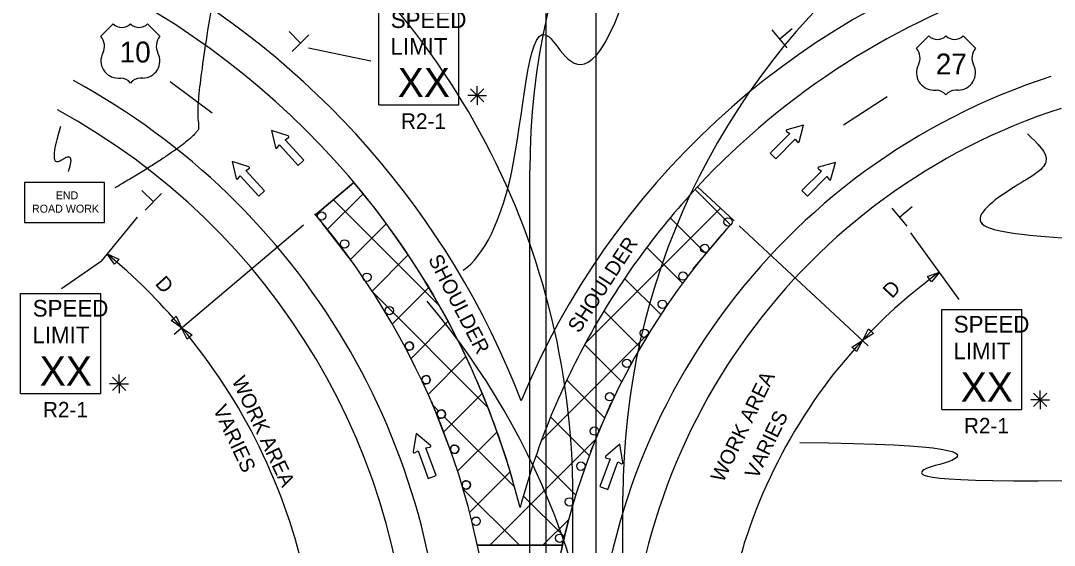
# Model space of a CAD drawing. Extents: x 16452 to 19504, y 5713 to 7079.
# Drawn here: x 16729 to 17224.4, y 6501.7 to 6753 of the extents above; entities that cross this region are included whole.
import ezdxf

# ---------------------------------------------------------------- set-up
doc = ezdxf.new("R2010")
doc.units = 0
for name, color, linetype in [('ALI_LEGAL_EX', 7, 'Continuous'), ('MT_SCRATCH_LEVEL_A', 7, 'Continuous'), ('MT_SCRATCH_LEVEL_E', 7, 'Continuous'), ('PAVT_EDGE_EX', 7, 'Continuous'), ('TRAFFIC_SIGNS_PR', 7, 'Continuous'), ('TYPICAL_EX', 7, 'Continuous'), ('TYPICAL_TEXT_DIMEN_PR', 7, 'Continuous')]:
    doc.layers.add(name, color=color, linetype=linetype)

msp = doc.modelspace()

# ---------------------------------------------------------------- linework, layer by layer
at = {"layer": 'ALI_LEGAL_EX'}
for p, q in [((16980.68, 7015.93), (16980.68, 6197.8)), ((17004.68, 7015.93), (17004.68, 6197.8)), ((16980.68, 6877.04), (16980.68, 6013.12)), ((17004.68, 6877.04), (17004.68, 6013.12)), ((16973.01, 6180.85), (16973.01, 6681.19)), ((16993.65, 6024.8), (16993.65, 6525.15)), ((17017.65, 6024.8), (17017.65, 6525.15))]:
    msp.add_line(p, q, dxfattribs=at)
for points in [[(16820.7, 6708.79), (16800.68, 6723.77)], [(17123.3, 6703.07), (17144.27, 6716.68)], [(16888.99, 6636.13), (16873.66, 6655.88)], [(17051.33, 6634.12), (17067.47, 6653.22)], [(16935.03, 6547.11), (16925.96, 6570.4)], [(17002.2, 6546.89), (17011.97, 6569.9)]]:
    msp.add_lwpolyline(points, dxfattribs=at)
for centre, radius, start, end in [((17313.01, 6681.19), 340, 129.5666, 180), ((16629.65, 6525.15), 364, 0, 57.2958), ((17357.65, 6525.15), 340, 129.5666, 180), ((16591.93, 6425.58), 364, 0, 40.1909), ((17319.93, 6425.58), 340, 137.516, 180), ((16645.75, 6383.76), 364, 0, 40.1909)]:
    msp.add_arc(centre, radius, start, end, dxfattribs=at)
at = {"layer": 'MT_SCRATCH_LEVEL_A'}
for p, q in [((16870.35, 6660.05), (16888.71, 6675.51)), ((16876.07, 6653.08), (16893.14, 6670.15)), ((17069.18, 6655.19), (17052.19, 6672.18)), ((17070.93, 6657.09), (17053.35, 6673.43)), ((16929.73, 6616.45), (16878.92, 6667.26)), ((16999.56, 6598.38), (17064.37, 6663.19)), ((16887.07, 6638.62), (16904.25, 6655.8)), ((17057.35, 6641.57), (17040.31, 6658.61)), ((17046.21, 6627.26), (17029.06, 6644.41)), ((16897.41, 6623.51), (16914.74, 6640.84)), ((17035.76, 6612.25), (17018.45, 6629.55)), ((16907.08, 6607.72), (16924.61, 6625.25)), ((16952.92, 6567.81), (16897.76, 6622.96)), ((17026.03, 6596.52), (17008.52, 6614.04)), ((16916.05, 6591.23), (16933.83, 6609.01)), ((16978.56, 6551.92), (17030.3, 6603.66)), ((17017.05, 6580.05), (16999.27, 6597.83)), ((16924.29, 6574.02), (16942.38, 6592.11)), ((17008.85, 6562.79), (16990.74, 6580.9)), ((16931.75, 6556.03), (16950.22, 6574.49)), ((16929.2, 6566.08), (16926.64, 6568.63)), ((16965.75, 6529.53), (16932.02, 6563.25)), ((17001.48, 6544.7), (16982.96, 6563.22)), ((16938.39, 6537.21), (16957.31, 6556.13)), ((16953.81, 6501.72), (17004.45, 6552.36)), ((16995.01, 6525.72), (16975.99, 6544.74)), ((16944.13, 6517.5), (16963.6, 6536.96)), ((16968.1, 6501.72), (16940.97, 6528.84)), ((16989.56, 6505.71), (16969.88, 6525.39)), ((16979.27, 6501.72), (16991.66, 6514.11)), ((16991.51, 6513.55), (16988.57, 6501.72))]:
    msp.add_line(p, q, dxfattribs=at)
for points in [[(16888.71, 6675.51), (16888.71, 6675.51), (16870.35, 6660.05)], [(17070.93, 6657.09), (17053.35, 6673.43), (17053.35, 6673.43)], [(16968.33, 6519.76), (16968.33, 6519.76), (16968.33, 6519.76)], [(16968.33, 6519.76), (16968.33, 6519.76)], [(16947.88, 6501.72), (16988.57, 6501.72), (16991.51, 6513.55)]]:
    msp.add_lwpolyline(points, dxfattribs=at)
for centre, radius, start, end in [((16591.93, 6425.58), 388, 28.2673, 40.102), ((17319.93, 6425.58), 364, 137.0843, 151.1372), ((16591.93, 6425.58), 388, 14.0483, 28.2673), ((16591.93, 6425.58), 388, 14.0483, 28.2673), ((16591.93, 6425.58), 388, 14.0483, 28.2673), ((17319.93, 6425.58), 364, 151.1372, 165.0045), ((17319.93, 6425.58), 364, 151.1372, 165.0044), ((17319.93, 6425.58), 364, 151.1372, 165.0044), ((16915.23, 6597.14), 2, 90, 205.9785), ((16915.23, 6597.14), 2, 209.93, 270), ((16915.23, 6597.14), 2, 270, 90), ((16923.27, 6581.04), 2, 90, 203.3612), ((16923.27, 6581.04), 2, 206.9117, 270), ((16923.27, 6581.04), 2, 270, 90), ((16930.51, 6564.57), 2, 90, 200.7992), ((16930.51, 6564.57), 2, 270, 90), ((16930.51, 6564.57), 2, 203.838, 270), ((16936.94, 6547.75), 2, 90, 198.3282), ((16936.94, 6547.75), 2, 200.6735, 270), ((16936.94, 6547.75), 2, 270, 90), ((16942.52, 6530.65), 2, 90, 196.0905), ((16942.52, 6530.65), 2, 270, 90), ((16942.52, 6530.65), 2, 197.2755, 270), ((17319.93, 6425.58), 364, 165.00447777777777, 165.0044972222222), ((16591.93, 6425.58), 388, 14.048225, 14.048227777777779), ((17319.93, 6425.58), 364, 165.0044, 165.0045)]:
    msp.add_arc(centre, radius, start, end, dxfattribs=at)
at = {"layer": 'MT_SCRATCH_LEVEL_E'}
for p, q in [((16857.2, 6697.82), (16849.25, 6700.35)), ((16849.25, 6700.35), (16851.12, 6692.23)), ((17097.56, 6698.96), (17088.21, 6689.56)), ((17096.08, 6699.99), (17097.56, 6698.96)), ((17104.24, 6703.05), (17096.22, 6700.81)), ((17102.07, 6694.99), (17104.24, 6703.05)), ((16855.79, 6696.02), (16857.31, 6696.99)), ((16864.75, 6686.25), (16855.79, 6696.02)), ((17090.86, 6686.92), (17100.21, 6696.32)), ((17100.21, 6696.32), (17101.25, 6694.84)), ((16851.94, 6692.05), (16853.03, 6693.49)), ((16853.03, 6693.49), (16862, 6683.72)), ((17088.21, 6689.56), (17090.86, 6686.92)), ((16838.3, 6683.02), (16830.35, 6685.55)), ((16830.35, 6685.55), (16832.22, 6677.44)), ((16862, 6683.72), (16864.75, 6686.25)), ((17119.47, 6685.09), (17111.45, 6682.86)), ((17117.3, 6677.03), (17119.47, 6685.09)), ((16836.89, 6681.22), (16838.41, 6682.19)), ((16845.86, 6671.46), (16836.89, 6681.22)), ((17112.79, 6681), (17103.44, 6671.6)), ((17111.31, 6682.03), (17112.79, 6681)), ((16833.04, 6677.26), (16834.14, 6678.69)), ((16834.14, 6678.69), (16843.1, 6668.93)), ((17106.09, 6668.96), (17115.44, 6678.36)), ((17115.44, 6678.36), (17116.48, 6676.89)), ((16843.1, 6668.93), (16845.86, 6671.46)), ((17103.44, 6671.6), (17106.09, 6668.96))]:
    msp.add_line(p, q, dxfattribs=at)
for centre, start, end in [((17096.35, 6700.36), 105.5821, 235.121), ((16857.05, 6697.37), 302.594, 72.331), ((17101.62, 6695.12), 215.1934, 344.9303), ((16851.57, 6692.34), 192.9827, 322.5217), ((16838.15, 6682.58), 302.594, 72.331), ((17111.58, 6682.41), 105.5821, 235.121), ((16832.67, 6677.55), 192.9827, 322.5217), ((17116.85, 6677.16), 215.1934, 344.9303)]:
    msp.add_arc(centre, 0.463, start, end, dxfattribs=at)
at = {"layer": 'PAVT_EDGE_EX'}
msp.add_line((16988.57, 6501.72), (16947.88, 6501.72), dxfattribs=at)
for centre, radius, start, end in [((17319.93, 6425.58), 380, 107.923, 157.5011), ((16591.93, 6425.58), 404, 21.0961, 61.4862), ((17319.93, 6425.58), 364, 107.923, 137.0843), ((16591.93, 6425.58), 388, 14.0482, 61.4862), ((16591.93, 6425.58), 340, 0, 61.4862), ((17319.93, 6425.58), 316, 107.923, 180), ((16591.93, 6425.58), 324, 0, 61.4862), ((17319.93, 6425.58), 300, 107.923, 180), ((17319.93, 6425.58), 340, 167.0592, 180)]:
    msp.add_arc(centre, radius, start, end, dxfattribs=at)
at = {"layer": 'TRAFFIC_SIGNS_PR'}
for p, q in [((16900.57, 6712.64), (16900.57, 6760.64)), ((16938.97, 6712.64), (16938.97, 6760.64)), ((16900.57, 6712.64), (16938.97, 6712.64)), ((16728.95, 6622.41), (16767.35, 6622.41)), ((16728.95, 6574.41), (16728.95, 6622.41)), ((16767.35, 6574.41), (16767.35, 6622.41)), ((17170.41, 6614.75), (17208.81, 6614.75)), ((17170.41, 6566.75), (17170.41, 6614.75)), ((17208.81, 6566.75), (17208.81, 6614.75)), ((16728.95, 6574.41), (16767.35, 6574.41)), ((17170.41, 6566.75), (17208.81, 6566.75))]:
    msp.add_line(p, q, dxfattribs=at)
msp.add_lwpolyline([(16730.76, 6656.32), (16769.16, 6656.32), (16769.16, 6675.52), (16730.76, 6675.52)], close=True, dxfattribs=at)
for centre in [(16873.23, 6659.48), (17067.98, 6656.63), (16884.19, 6646.08), (17056.86, 6643.93), (16894.93, 6630.13), (17046.37, 6630.65), (16905.68, 6614.18), (17036.58, 6617.2), (17027.91, 6603.29), (16915.23, 6597.14), (17019.45, 6588.91), (16923.27, 6581.04), (17011.28, 6572.88), (16930.51, 6564.57), (17003.96, 6556.44), (16936.94, 6547.75), (16997.51, 6539.63), (16942.52, 6530.65), (16991.96, 6522.51), (16947.27, 6513.28), (16987.31, 6505.13)]:
    msp.add_circle(centre, 2, dxfattribs=at)
at = {"layer": 'TYPICAL_EX'}
for p, q in [((16767.4, 6745.56), (16773.29, 6751.46)), ((16795.7, 6745.56), (16789.8, 6751.46)), ((17158.32, 6739.84), (17164.22, 6745.74)), ((17186.62, 6739.84), (17180.72, 6745.74)), ((16775.64, 6725.5), (16776.82, 6725.5)), ((16787.45, 6725.5), (16786.27, 6725.5)), ((17166.57, 6719.78), (17167.75, 6719.78)), ((17178.37, 6719.78), (17177.19, 6719.78))]:
    msp.add_line(p, q, dxfattribs=at)
for centre, radius, start, end in [((16777.42, 6755.75), 5.96, 226.1404, 313.8596), ((16785.67, 6755.75), 5.96, 226.1404, 313.8596), ((16761.81, 6740.84), 7.31, 333.0977, 40.1936), ((16801.28, 6740.84), 7.31, 139.8064, 206.9023), ((17168.34, 6750.03), 5.96, 226.1404, 313.8596), ((17176.6, 6750.03), 5.96, 226.1404, 313.8596), ((17152.73, 6735.12), 7.31, 333.0977, 40.1936), ((17192.21, 6735.12), 7.31, 139.8064, 206.9023), ((16775.66, 6733.75), 8.24, 152.6698, 269.9013), ((16787.43, 6733.75), 8.24, 270.0987, 27.3302), ((17166.58, 6728.03), 8.24, 152.6698, 269.9013), ((17178.36, 6728.03), 8.24, 270.0987, 27.3302), ((16776.84, 6719.6), 5.91, 37.1038, 90.1385), ((16786.26, 6719.6), 5.91, 89.8615, 142.8962), ((17167.76, 6713.88), 5.91, 37.1038, 90.1385), ((17177.18, 6713.88), 5.91, 89.8615, 142.8962)]:
    msp.add_arc(centre, radius, start, end, dxfattribs=at)
at = {"layer": 'TYPICAL_TEXT_DIMEN_PR'}
for p, q in [((17096.38, 6739.96), (17089.19, 6748.62)), ((17092.79, 6744.29), (17098.78, 6749.26)), ((16863.11, 6742.3), (16857.59, 6747.8)), ((16867.08, 6746.29), (16859.14, 6738.32)), ((16866.93, 6739.96), (16896.78, 6733.83)), ((16944.57, 6720.44), (16950.95, 6714.07)), ((16950.95, 6720.44), (16944.57, 6714.07)), ((16947.76, 6717.25), (16947.76, 6721.71)), ((16947.76, 6717.25), (16943.23, 6717.25)), ((16947.76, 6717.25), (16950.95, 6717.25)), ((16947.76, 6717.25), (16952.24, 6717.25)), ((16947.76, 6717.25), (16947.76, 6712.75)), ((16792.55, 6666.21), (16787.03, 6671.71)), ((16796.52, 6670.2), (16788.58, 6662.23)), ((17150.22, 6658.96), (17156.21, 6663.94)), ((17153.81, 6654.64), (17146.62, 6663.29)), ((16767.65, 6637.9), (16785.02, 6658.89)), ((16802.5, 6602.91), (16864.56, 6655.17)), ((17135.22, 6597.31), (17073.41, 6654.78)), ((17178.86, 6619.51), (17155.62, 6651.46)), ((16773.97, 6636.34), (16770.45, 6641.28)), ((16770.45, 6641.28), (16775.97, 6638.76)), ((16767.65, 6637.9), (16748.52, 6624.5)), ((16774.97, 6637.55), (16773.97, 6636.34)), ((16775.97, 6638.76), (16774.97, 6637.55)), ((17163.67, 6630.42), (17169.34, 6632.6)), ((17164.6, 6629.15), (17163.67, 6630.42)), ((17169.34, 6632.6), (17165.52, 6627.88)), ((17165.52, 6627.88), (17164.6, 6629.15)), ((16801.12, 6609.41), (16802.33, 6610.42)), ((16806.1, 6605.94), (16801.12, 6609.41)), ((16802.33, 6610.42), (16803.53, 6611.43)), ((16803.53, 6611.43), (16806.1, 6605.94)), ((16808.68, 6600.44), (16806.1, 6605.94)), ((16806.1, 6605.94), (16811.08, 6602.47)), ((17132.55, 6600), (17135.39, 6605.36)), ((17135.39, 6605.36), (17136.54, 6604.29)), ((16809.88, 6601.45), (16808.68, 6600.44)), ((16811.08, 6602.47), (16809.88, 6601.45)), ((17127.31, 6596.67), (17132.45, 6599.89)), ((17132.45, 6599.89), (17129.61, 6594.53)), ((17137.69, 6603.22), (17132.55, 6600)), ((17136.54, 6604.29), (17137.69, 6603.22)), ((17128.46, 6595.6), (17127.31, 6596.67)), ((17129.61, 6594.53), (17128.46, 6595.6)), ((16779.33, 6582.21), (16772.95, 6575.83)), ((16772.96, 6582.21), (16779.33, 6575.83)), ((16776.14, 6579.02), (16776.14, 6583.48)), ((16776.14, 6579.02), (16771.61, 6579.02)), ((16776.14, 6579.02), (16779.33, 6579.02)), ((16776.14, 6579.02), (16780.62, 6579.02)), ((16776.14, 6579.02), (16776.14, 6574.52)), ((17217.6, 6571.36), (17217.6, 6575.82)), ((17217.6, 6571.36), (17213.07, 6571.36)), ((17214.41, 6574.55), (17220.79, 6568.18)), ((17220.79, 6574.55), (17214.41, 6568.18)), ((17217.6, 6571.36), (17220.79, 6571.36)), ((17217.6, 6571.36), (17222.08, 6571.36)), ((17217.6, 6571.36), (17217.6, 6566.86)), ((16918.54, 6555.32), (16917.06, 6546.56)), ((16925.34, 6549.57), (16918.54, 6555.32)), ((17016.14, 6550.09), (17009.36, 6544.35)), ((17017.63, 6541.31), (17016.14, 6550.09)), ((16917.79, 6546.05), (16919.46, 6547.01)), ((16919.46, 6547.01), (16924.29, 6533.72)), ((16923.21, 6548.38), (16925.11, 6548.71)), ((16928.04, 6535.09), (16923.21, 6548.38)), ((17011.49, 6543.15), (17006.61, 6529.88)), ((17009.59, 6543.49), (17011.49, 6543.15)), ((17010.35, 6528.5), (17015.23, 6541.77)), ((17015.23, 6541.77), (17016.9, 6540.8)), ((16924.29, 6533.72), (16928.04, 6535.09)), ((17006.61, 6529.88), (17010.35, 6528.5))]:
    msp.add_line(p, q, dxfattribs=at)
for centre, radius, start, end in [((16591.93, 6425.58), 280, 40.102, 50.3886), ((17319.93, 6425.58), 256, 126.0328, 137.0506), ((16591.93, 6425.58), 280, 12.0744, 40.102), ((17319.93, 6425.58), 256, 137.0843, 167.0592), ((16917.55, 6546.48), 0.494, 170.4097, 299.9487), ((16925.01, 6549.2), 0.494, 280.0211, 49.758), ((17009.69, 6543.98), 0.494, 130.2465, 259.7854), ((17017.14, 6541.24), 0.494, 239.8578, 9.5947)]:
    msp.add_arc(centre, radius, start, end, dxfattribs=at)
for points, degree in [([(16941.05, 6633.46), (16950.74, 6640.19), (16968.86, 6673.36), (16974.2, 6794.28), (17010.05, 6678.73), (17050.4, 6901.53)], 3), ([(16865.54, 6839.9), (16831.8, 6826.12), (16811.54, 6708.24), (16817.3, 6698.14), (16774.14, 6672.9)], 2), ([(16751.84, 6680.83), (16755.44, 6690.93), (16741.77, 6681.55), (16748.25, 6702.47)], 2), ([(17211.47, 6698.86), (17216.36, 6694.28), (17226.42, 6684.87), (17205.46, 6674.43), (17175.74, 6652.75), (17212.37, 6650.16), (17237.36, 6648.38)], 3), ([(17102.5, 6550.98), (17180.22, 6550.21), (17180.72, 6541.36), (17158.24, 6539.53), (17158, 6531.44), (17245.46, 6532.97)], 3)]:
    msp.add_open_spline(points, degree=degree, dxfattribs=at)

# ---------------------------------------------------------------- texts
at = {"layer": 'TRAFFIC_SIGNS_PR'}
for s, height, p in [('SPEED', 8, (16906.34, 6749.5)), ('LIMIT', 8, (16906.18, 6736.7)), ('XX', 14.031, (16909.69, 6716.4)), ('R2-1', 7.44, (16911.25, 6701.2)), ('END', 3.831, (16745.76, 6667.44)), ('ROAD WORK', 3.831, (16734.37, 6661.06)), ('SPEED', 8, (16734.72, 6611.27)), ('SPEED', 8, (17176.18, 6603.61)), ('LIMIT', 8, (16734.56, 6598.47)), ('LIMIT', 8, (17176.02, 6590.81)), ('XX', 14.031, (16738.07, 6578.17)), ('XX', 14.031, (17179.53, 6570.51)), ('R2-1', 7.44, (16739.63, 6562.97)), ('R2-1', 7.44, (17181.09, 6555.31))]:
    msp.add_text(s, height=height, dxfattribs=at).set_placement(p)
at = {"layer": 'TYPICAL_EX'}
for s, p in [('10', (16776.39, 6732.99)), ('27', (17167.58, 6727.27))]:
    msp.add_text(s, height=10, dxfattribs=at).set_placement(p)
at = {"layer": 'TYPICAL_TEXT_DIMEN_PR'}
for s, rotation, p in [('SHOULDER', 56.8597, (16996.61, 6602.97)), ('SHOULDER', 297.2217, (16924.12, 6638.83)), ('D', 312.2189, (16793.06, 6626.81)), ('D', 46.9245, (17146.62, 6619.61)), ('WORK AREA', 295.1762, (16829.99, 6580.73)), ('WORK AREA', 64.0878, (17065.65, 6531.39)), ('VARIES', 295.1762, (16820.99, 6566.96)), ('VARIES', 64.0878, (17082.01, 6533.05))]:
    msp.add_text(s, height=7, rotation=rotation, dxfattribs=at).set_placement(p)

doc.saveas('drawing.dxf')
